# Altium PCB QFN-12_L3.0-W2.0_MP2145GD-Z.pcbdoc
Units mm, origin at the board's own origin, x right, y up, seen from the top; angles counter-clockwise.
Board outline 16.18 x 15.56 mm, 2 copper layers (Top Layer, Bottom Layer), stack 0 mm thick; 1 components, 0 nets, 14 pads, 0 vias.
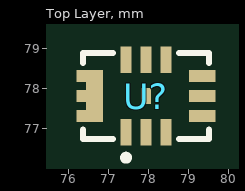
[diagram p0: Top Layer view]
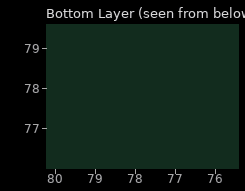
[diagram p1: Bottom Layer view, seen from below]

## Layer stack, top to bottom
Top Layer: signal copper (thickness not stored)
Bottom Layer: signal copper (thickness not stored)

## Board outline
86.03,69.85 69.85,69.85 69.85,85.405 86.03,85.405

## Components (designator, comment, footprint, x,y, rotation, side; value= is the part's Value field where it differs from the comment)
U? "" QFN-12_L3.0-W2.0_MP2145GD-Z 77.94,77.815 r0 top

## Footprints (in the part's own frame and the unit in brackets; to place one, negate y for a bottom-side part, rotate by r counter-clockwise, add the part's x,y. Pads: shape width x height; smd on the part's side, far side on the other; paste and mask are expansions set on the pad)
QFN-12_L3.0-W2.0_MP2145GD-Z [mm]
  rect 0.28x0.665 smd paste-100 mask+0.051: 1(-0.5,-0.908) 2(0,-0.908) 3(0.5,-0.908) 7(0.5,0.907) 8(0,0.907) 9(-0.5,0.907)
  rect 0.665x0.298 smd paste-100 mask+0.051: 4(1.407,-0.5) 5(1.407,0) 6(1.407,0.5) 10(-1.407,0.5) 11(-1.407,0) 12(-1.407,-0.5)
  rect 0.425x1.298 smd paste-100 mask+0.05: 11(-1.287,0)
  rect 0.25x0.4 smd paste-100 mask+0.051: 13(0,0)
  silkscreen extent -1.58,-1.61 1.58,1.08

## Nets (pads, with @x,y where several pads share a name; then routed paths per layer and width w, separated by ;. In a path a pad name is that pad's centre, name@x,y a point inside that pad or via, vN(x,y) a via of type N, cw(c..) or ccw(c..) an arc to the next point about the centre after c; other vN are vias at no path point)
pads on no net: U?.1 U?.2 U?.3 U?.4 U?.5 U?.6 U?.7 U?.8 U?.9 U?.10 U?.11 U?.12 U?.13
